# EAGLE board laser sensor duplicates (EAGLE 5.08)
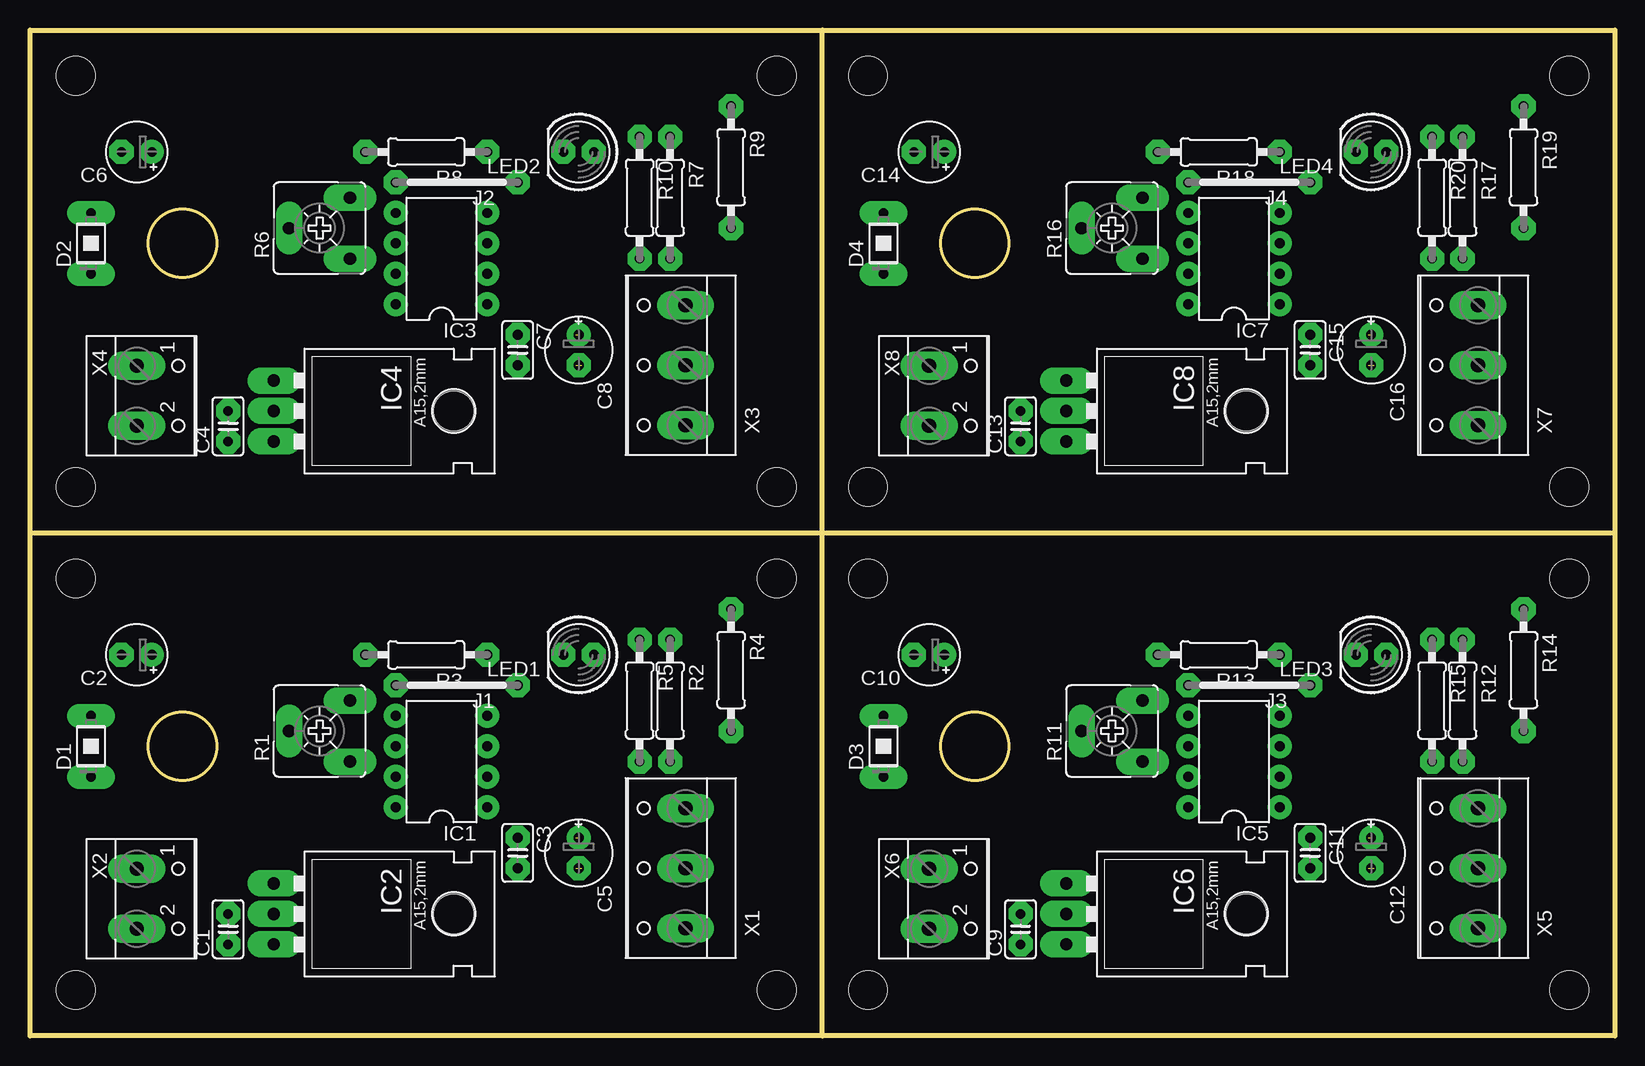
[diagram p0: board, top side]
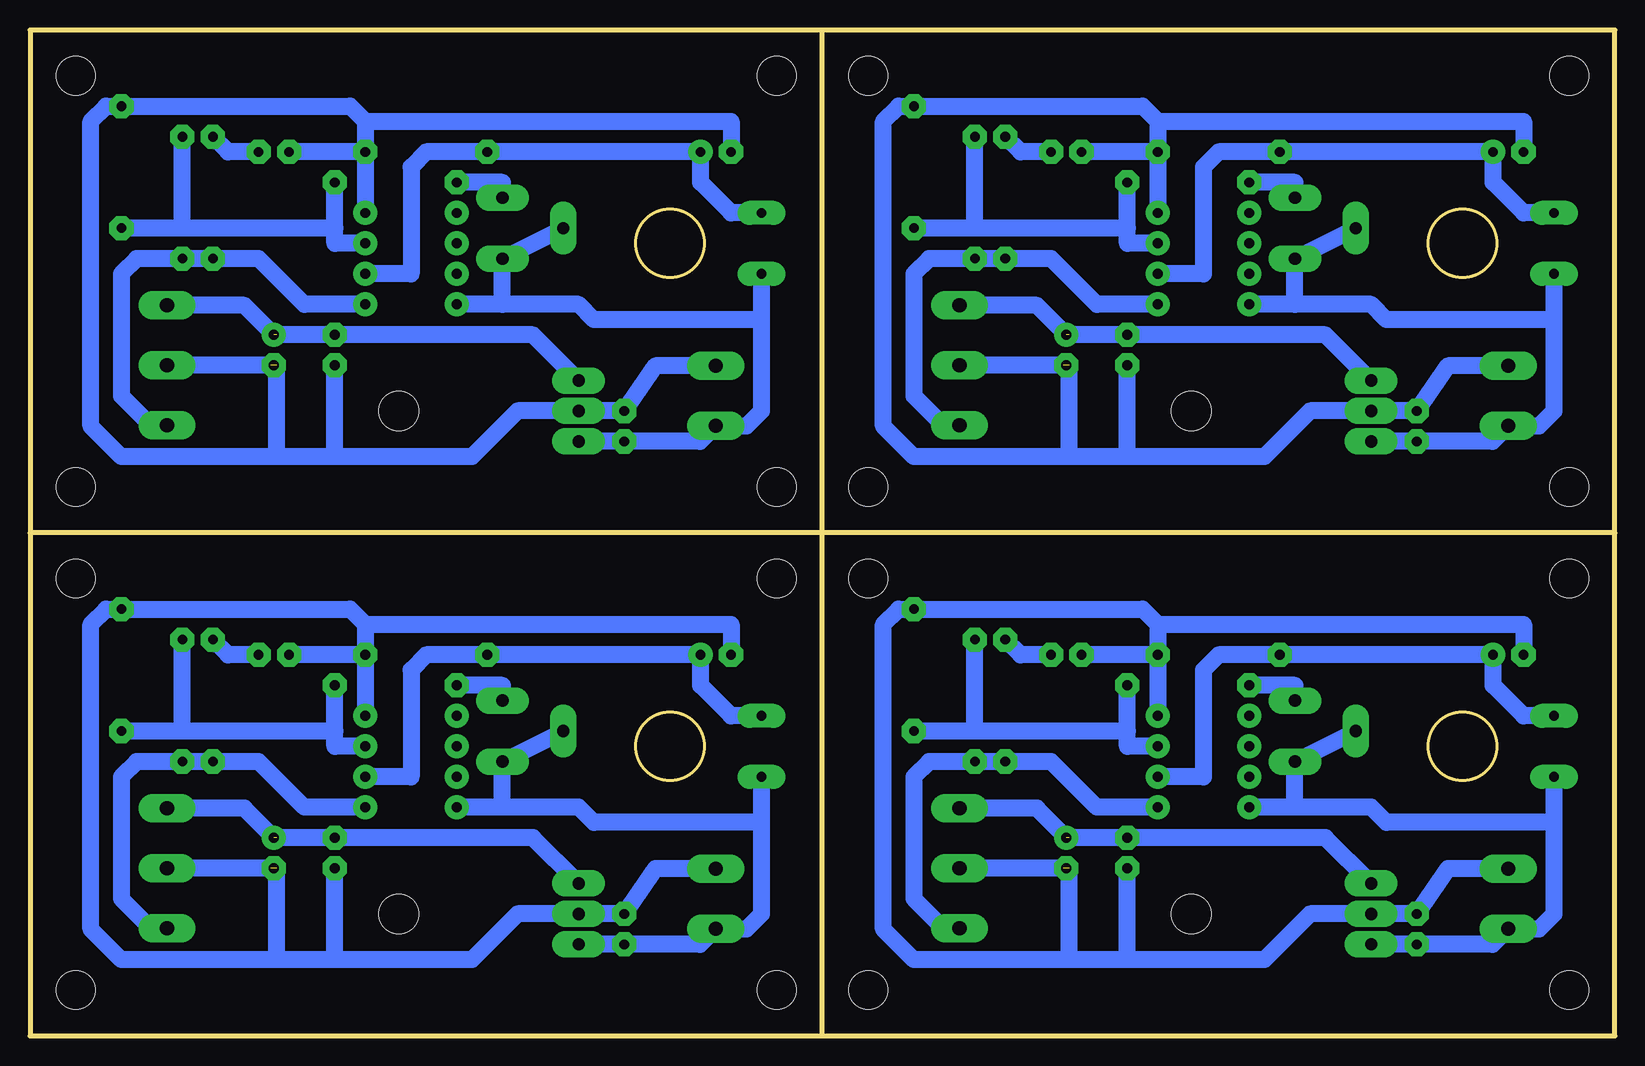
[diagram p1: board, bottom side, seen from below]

Size 132.08 x 83.82 mm. Coordinates in mm from the lower left corner, seen from the top.
Outline: 0,41.91 0,0 66.04,0
Outline: 0,41.91 0,83.82 66.04,83.82
Outline: 66.04,83.82 132.08,83.82 132.08,41.91
Outline: 132.08,41.91 132.08,0 66.04,0
Outline: 66.04,0 66.04,83.82
Outline: 0,41.91 132.08,41.91
Outline: circle at 12.7,24.13 radius 2.84
Outline: circle at 12.7,66.04 radius 2.84
Outline: circle at 78.74,24.13 radius 2.84
Outline: circle at 78.74,66.04 radius 2.84
Copper layers (1*16): Top 1mm / dielectric 1.5mm / Bottom 1mm
Design rules "DRC settings middle": minimum track width 1.2mm, minimum drill 24mil, track to track 0.4mm, track to pad 0.4mm, pad to pad 0.4mm, via to via 0.4mm, smd to smd 8mil, copper to edge 0.5mm, drill to drill 0.5mm, minimum pad ring 0.6mm, minimum via ring 1mm, stop-mask expansion 4mil, vias tented up to drill 0mil, thermal gap 10mil
Holes 3.2 mm at 62.23,38.1 3.81,38.1 3.81,3.81 62.23,3.81 62.23,80.01 3.81,80.01 3.81,45.72 62.23,45.72 128.27,38.1 69.85,38.1 69.85,3.81 128.27,3.81 128.27,80.01 69.85,80.01 69.85,45.72 128.27,45.72

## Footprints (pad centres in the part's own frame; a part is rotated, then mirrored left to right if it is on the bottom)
C025-025X050 = drill 0.813 octagon: 1 -1.27,0; 2 1.27,0
E2,5-5 = drill 0.813 pad 1.6 round: + -1.27,0 | drill 0.813 pad 1.6 octagon: - 1.27,0
E2,5-6E = drill 0.813 pad 1.575 round: + -1.27,0 | drill 0.813 pad 1.575 octagon: - 1.27,0
BPW32 = drill 0.813 long: A 0,2.54; K 0,-2.54
DIL08 = drill 0.813 pad 1.27 round: 1 -3.81,-3.81; 2 -1.27,-3.81; 3 1.27,-3.81; 4 3.81,-3.81; 5 3.81,3.81; 6 1.27,3.81; 7 -1.27,3.81; 8 -3.81,3.81
78XXL = drill 1.016 long: GND 0,-3.81; IN -2.54,-3.81; OUT 2.54,-3.81 | hole 3.302: 0,11.176
10 = drill 0.813 pad 1.6 octagon: 1 -5.08,0; 2 5.08,0
LED5MM = drill 0.813 octagon: A -1.27,0; K 1.27,0
CA6V = drill 1.016 long: A -2.54,-2.54; E 2.54,-2.54; S 0,2.54
0207/10 = drill 0.813 octagon: 1 -5.08,0; 2 5.08,0
W237-103 = drill 1.194 long: 1 -5,-1.29; 2 0,-1.29; 3 5,-1.29
W237-102 = drill 1.194 long: 1 -2.5,-1.27; 2 2.5,-1.27

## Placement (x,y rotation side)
C1  100nF  [C025-025X050]  16.51,8.89 90 top
C2  10uF  [E2,5-5]  8.89,31.75 180 top
C3  100nF  [C025-025X050]  40.64,15.24 270 top
C4  100nF  [C025-025X050]  16.51,50.8 90 top
C5  100uF  [E2,5-6E]  45.72,15.24 270 top
C6  10uF  [E2,5-5]  8.89,73.66 180 top
C7  100nF  [C025-025X050]  40.64,57.15 270 top
C8  100uF  [E2,5-6E]  45.72,57.15 270 top
C9  100nF  [C025-025X050]  82.55,8.89 90 top
C10  10uF  [E2,5-5]  74.93,31.75 180 top
C11  100nF  [C025-025X050]  106.68,15.24 270 top
C12  100uF  [E2,5-6E]  111.76,15.24 270 top
C13  100nF  [C025-025X050]  82.55,50.8 90 top
C14  10uF  [E2,5-5]  74.93,73.66 180 top
C15  100nF  [C025-025X050]  106.68,57.15 270 top
C16  100uF  [E2,5-6E]  111.76,57.15 270 top
D1  BPW32  [BPW32]  5.08,24.13 0 top
D2  BPW32  [BPW32]  5.08,66.04 0 top
D3  BPW32  [BPW32]  71.12,24.13 0 top
D4  BPW32  [BPW32]  71.12,66.04 0 top
IC1  TL072P  [DIL08]  34.29,22.86 90 top
IC2  7805  [78XXL]  24.13,10.16 270 top
IC3  TL072P  [DIL08]  34.29,64.77 90 top
IC4  7805  [78XXL]  24.13,52.07 270 top
IC5  TL072P  [DIL08]  100.33,22.86 90 top
IC6  7805  [78XXL]  90.17,10.16 270 top
IC7  TL072P  [DIL08]  100.33,64.77 90 top
IC8  7805  [78XXL]  90.17,52.07 270 top
J1  J10MM  [10]  35.56,29.21 180 top
J2  J10MM  [10]  35.56,71.12 180 top
J3  J10MM  [10]  101.6,29.21 180 top
J4  J10MM  [10]  101.6,71.12 180 top
LED1  [LED5MM]  45.72,31.75 180 top
LED2  [LED5MM]  45.72,73.66 180 top
LED3  [LED5MM]  111.76,31.75 180 top
LED4  [LED5MM]  111.76,73.66 180 top
R1  [CA6V]  24.13,25.4 90 top
R2  33K  [0207/10]  53.34,27.94 270 top
R3  10K  [0207/10]  33.02,31.75 180 top
R4  10K  [0207/10]  58.42,30.48 270 top
R5  470  [0207/10]  50.8,27.94 270 top
R6  [CA6V]  24.13,67.31 90 top
R7  33K  [0207/10]  53.34,69.85 270 top
R8  10K  [0207/10]  33.02,73.66 180 top
R9  10K  [0207/10]  58.42,72.39 270 top
R10  470  [0207/10]  50.8,69.85 270 top
R11  [CA6V]  90.17,25.4 90 top
R12  33K  [0207/10]  119.38,27.94 270 top
R13  10K  [0207/10]  99.06,31.75 180 top
R14  10K  [0207/10]  124.46,30.48 270 top
R15  470  [0207/10]  116.84,27.94 270 top
R16  [CA6V]  90.17,67.31 90 top
R17  33K  [0207/10]  119.38,69.85 270 top
R18  10K  [0207/10]  99.06,73.66 180 top
R19  10K  [0207/10]  124.46,72.39 270 top
R20  470  [0207/10]  116.84,69.85 270 top
X1  [W237-103]  53.34,13.97 90 top
X2  [W237-102]  10.16,11.43 270 top
X3  [W237-103]  53.34,55.88 90 top
X4  [W237-102]  10.16,53.34 270 top
X5  [W237-103]  119.38,13.97 90 top
X6  [W237-102]  76.2,11.43 270 top
X7  [W237-103]  119.38,55.88 90 top
X8  [W237-102]  76.2,53.34 270 top

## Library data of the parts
C1-C16 R2-R5 R7-R10 R12-R15 R17-R20 = rcl
D1-D4 = opto-trans-siemens
IC1 IC3 IC5 IC7 = linear
IC2 IC4 IC6 IC8 = v-reg
J1-J4 = jumper
LED1-LED4 = led
R1 R6 R11 R16 = pot
X1-X8 = con-wago-500

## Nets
+5V: C1.1 D1.K IC1.8 IC2.OUT R1.A R1.S X2.2
+5V1: C4.1 D2.K IC3.8 IC4.OUT R6.A R6.S X4.2
+5V2: C9.1 D3.K IC5.8 IC6.OUT R11.A R11.S X6.2
+5V3: C13.1 D4.K IC7.8 IC8.OUT R16.A R16.S X8.2
+12V: C3.1 C5.+ IC2.IN X1.3
+12V1: C7.1 C8.+ IC4.IN X3.3
+12V2: C11.1 C12.+ IC6.IN X5.3
+12V3: C15.1 C16.+ IC8.IN X7.3
GND: C1.2 C2.- C3.2 C5.- IC1.4 IC2.GND LED1.K R3.1 R4.1 X1.2 X2.1
GND1: C4.2 C6.- C7.2 C8.- IC3.4 IC4.GND LED2.K R8.1 R9.1 X3.2 X4.1
GND2: C9.2 C10.- C11.2 C12.- IC5.4 IC6.GND LED3.K R13.1 R14.1 X5.2 X6.1
GND3: C13.2 C14.- C15.2 C16.- IC7.4 IC8.GND LED4.K R18.1 R19.1 X7.2 X8.1
N$1: IC1.3 J1.1 R2.1 R4.2
N$2: IC1.1 R2.2 R5.2 X1.1
N$3: LED1.A R5.1
N$4: C2.+ D1.A IC1.2 R3.2
N$5: J1.2 R1.E
N$6: IC3.3 J2.1 R7.1 R9.2
N$7: IC3.1 R7.2 R10.2 X3.1
N$8: C6.+ D2.A IC3.2 R8.2
N$9: LED2.A R10.1
N$10: J2.2 R6.E
N$11: IC5.3 J3.1 R12.1 R14.2
N$12: IC5.1 R12.2 R15.2 X5.1
N$13: C10.+ D3.A IC5.2 R13.2
N$14: LED3.A R15.1
N$15: J3.2 R11.E
N$16: IC7.3 J4.1 R17.1 R19.2
N$17: IC7.1 R17.2 R20.2 X7.1
N$18: C14.+ D4.A IC7.2 R18.2
N$19: LED4.A R20.1
N$20: J4.2 R16.E

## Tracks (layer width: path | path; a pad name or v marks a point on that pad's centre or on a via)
+5V
  Bottom 1.422: IC2.OUT C1.1 10.2,7.62 X2.2 8.85,8.89 6.35,8.89 5.08,10.16 5.08,17.78 | 26.67,19.05 IC1.8 | 26.67,19.05 R1.A R1.S | 5.08,17.78 D1.K | 26.67,19.05 20.32,19.05 19.05,17.78 5.08,17.78
+5V1
  Bottom 1.422: IC4.OUT C4.1 10.2,49.53 X4.2 8.85,50.8 6.35,50.8 5.08,52.07 5.08,59.69 | 26.67,60.96 IC3.8 | 26.67,60.96 R6.A R6.S | 5.08,59.69 D2.K | 26.67,60.96 20.32,60.96 19.05,59.69 5.08,59.69
+5V2
  Bottom 1.422: IC6.OUT C9.1 76.24,7.62 X6.2 74.89,8.89 72.39,8.89 71.12,10.16 71.12,17.78 | 92.71,19.05 IC5.8 | 92.71,19.05 R11.A R11.S | 71.12,17.78 D3.K | 92.71,19.05 86.36,19.05 85.09,17.78 71.12,17.78
+5V3
  Bottom 1.422: IC8.OUT C13.1 76.24,49.53 X8.2 74.89,50.8 72.39,50.8 71.12,52.07 71.12,59.69 | 92.71,60.96 IC7.8 | 92.71,60.96 R16.A R16.S | 71.12,59.69 D4.K | 92.71,60.96 86.36,60.96 85.09,59.69 71.12,59.69
+12V  (1 unrouted)
  Bottom 1.422: 45.47,16.51 C3.1 24.13,16.51 IC2.IN | X1.3 48.18,18.97 C5.+
+12V1  (1 unrouted)
  Bottom 1.422: 45.47,58.42 C7.1 24.13,58.42 IC4.IN | X3.3 48.18,60.88 C8.+
+12V2  (1 unrouted)
  Bottom 1.422: 111.51,16.51 C11.1 90.17,16.51 IC6.IN | X5.3 114.22,18.97 C12.+
+12V3  (1 unrouted)
  Bottom 1.422: 111.51,58.42 C15.1 90.17,58.42 IC8.IN | X7.3 114.22,60.88 C16.+
GND  (2 unrouted)
  Bottom 1.422: X2.1 13.93,13.93 C1.2 IC2.GND 25.4,10.16 29.21,6.35 40.64,6.35 | R3.1 LED1.K | R3.1 IC1.4 | 45.97,13.97 X1.2 | 38.1,34.29 R3.1 | C2.- 7.62,34.29 38.1,34.29 | 38.1,34.29 39.37,35.56 R4.1 59.69,35.56 60.96,34.29 60.96,8.89 58.42,6.35 45.72,6.35 | 40.64,6.35 45.72,6.35 | 40.64,6.35 C3.2 | 45.47,13.97 45.47,6.6 45.72,6.35
GND1  (2 unrouted)
  Bottom 1.422: X4.1 13.93,55.84 C4.2 IC4.GND 25.4,52.07 29.21,48.26 40.64,48.26 | R8.1 LED2.K | R8.1 IC3.4 | 45.97,55.88 X3.2 | 38.1,76.2 R8.1 | C6.- 7.62,76.2 38.1,76.2 | 38.1,76.2 39.37,77.47 R9.1 59.69,77.47 60.96,76.2 60.96,50.8 58.42,48.26 45.72,48.26 | 40.64,48.26 45.72,48.26 | 40.64,48.26 C7.2 | 45.47,55.88 45.47,48.51 45.72,48.26
GND2  (2 unrouted)
  Bottom 1.422: X6.1 79.97,13.93 C9.2 IC6.GND 91.44,10.16 95.25,6.35 106.68,6.35 | R13.1 LED3.K | R13.1 IC5.4 | 112.01,13.97 X5.2 | 104.14,34.29 R13.1 | C10.- 73.66,34.29 104.14,34.29 | 104.14,34.29 105.41,35.56 R14.1 125.73,35.56 127,34.29 127,8.89 124.46,6.35 111.76,6.35 | 106.68,6.35 111.76,6.35 | 106.68,6.35 C11.2 | 111.51,13.97 111.51,6.6 111.76,6.35
GND3  (2 unrouted)
  Bottom 1.422: X8.1 79.97,55.84 C13.2 IC8.GND 91.44,52.07 95.25,48.26 106.68,48.26 | R18.1 LED4.K | R18.1 IC7.4 | 112.01,55.88 X7.2 | 104.14,76.2 R18.1 | C14.- 73.66,76.2 104.14,76.2 | 104.14,76.2 105.41,77.47 R19.1 125.73,77.47 127,76.2 127,50.8 124.46,48.26 111.76,48.26 | 106.68,48.26 111.76,48.26 | 106.68,48.26 C15.2 | 111.51,55.88 111.51,48.51 111.76,48.26
N$1
  Bottom 1.422: IC1.3 40.64,24.13 40.64,25.4 | 40.64,25.4 J1.1 | 40.64,25.4 53.34,25.4 | 53.34,25.4 R4.2 | 53.34,25.4 R2.1
N$2
  Bottom 1.422: X1.1 54.71,8.89 55.88,8.89 58.42,11.43 58.42,21.59 57.15,22.86 R2.2 R5.2 46.99,22.86 43.18,19.05 IC1.1
N$3
  Bottom 1.422: LED1.A 49.53,31.75 R5.1
N$4
  Bottom 1.422: IC1.2 34.29,21.59 34.29,30.48 33.02,31.75 R3.2 C2.+ 10.16,29.21 7.62,26.67 D1.A
N$5
  Bottom 1.422: J1.2 26.67,29.21 R1.E
N$6
  Bottom 1.422: IC3.3 40.64,66.04 40.64,67.31 | 40.64,67.31 J2.1 | 40.64,67.31 53.34,67.31 | 53.34,67.31 R9.2 | 53.34,67.31 R7.1
N$7
  Bottom 1.422: X3.1 54.71,50.8 55.88,50.8 58.42,53.34 58.42,63.5 57.15,64.77 R7.2 R10.2 46.99,64.77 43.18,60.96 IC3.1
N$8
  Bottom 1.422: IC3.2 34.29,63.5 34.29,72.39 33.02,73.66 R8.2 C6.+ 10.16,71.12 7.62,68.58 D2.A
N$9
  Bottom 1.422: LED2.A 49.53,73.66 R10.1
N$10
  Bottom 1.422: J2.2 26.67,71.12 R6.E
N$11
  Bottom 1.422: IC5.3 106.68,24.13 106.68,25.4 | 106.68,25.4 J3.1 | 106.68,25.4 119.38,25.4 | 119.38,25.4 R14.2 | 119.38,25.4 R12.1
N$12
  Bottom 1.422: X5.1 120.75,8.89 121.92,8.89 124.46,11.43 124.46,21.59 123.19,22.86 R12.2 R15.2 113.03,22.86 109.22,19.05 IC5.1
N$13
  Bottom 1.422: IC5.2 100.33,21.59 100.33,30.48 99.06,31.75 R13.2 C10.+ 76.2,29.21 73.66,26.67 D3.A
N$14
  Bottom 1.422: LED3.A 115.57,31.75 R15.1
N$15
  Bottom 1.422: J3.2 92.71,29.21 R11.E
N$16
  Bottom 1.422: IC7.3 106.68,66.04 106.68,67.31 | 106.68,67.31 J4.1 | 106.68,67.31 119.38,67.31 | 119.38,67.31 R19.2 | 119.38,67.31 R17.1
N$17
  Bottom 1.422: X7.1 120.75,50.8 121.92,50.8 124.46,53.34 124.46,63.5 123.19,64.77 R17.2 R20.2 113.03,64.77 109.22,60.96 IC7.1
N$18
  Bottom 1.422: IC7.2 100.33,63.5 100.33,72.39 99.06,73.66 R18.2 C14.+ 76.2,71.12 73.66,68.58 D4.A
N$19
  Bottom 1.422: LED4.A 115.57,73.66 R20.1
N$20
  Bottom 1.422: J4.2 92.71,71.12 R16.E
